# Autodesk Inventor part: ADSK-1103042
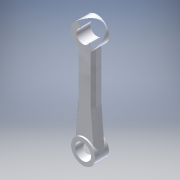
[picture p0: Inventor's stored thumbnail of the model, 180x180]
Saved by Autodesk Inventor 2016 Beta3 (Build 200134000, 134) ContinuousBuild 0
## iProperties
Shininess: 50.0
Length Units: 11272
Angle Units: 11279
Time Units: 11290
Mass Units: 11286
Length Display Precision: 4
Angle Display Precision: 2
Compacted: True
Created: 2000-11
Part Number: ADSK-1103042
Document SubType Name: Modeling
Description: CONNECTING ROD
Mass: 0.815863 g
Surface Area: 4.69105 cm^2
Volume: 0.301057 cm^3
Density: 2.71 g/cm^3
Material: Aluminum-6061
Appearance: Aluminum - Flat
Density: 0.0
Volumn: 0.0
Area: 0.0
PropertySet Name: Model Information
Control State: 0
Master: False
Checked Out: False
Author: Autodesk, Inc.
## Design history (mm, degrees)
node "Extrusion1" dims "d8" = 2.54, "d9" = 0
  sketch "Sketch2"
    geometry: L1 (-7.585, -9.592)-(-6.801, -0.307); L2 (-6.801, -0.307)-(-6.801, 11.849); L3 (-2.674, 11.849)-(-2.674, -0.307); L4 (-2.674, -0.307)-(-1.89, -9.592); C1 r 1.905 at (-4.737, -9.832); C2 r 1.587 at (-4.737, 13.917); C3 r 2.064 at (-4.737, 13.917); A1 r 2.857 centre (-4.737, -9.832) between (-7.585, -9.592) and (-1.89, -9.592); A2 r 2.921 centre (-4.737, 13.917) between (-2.674, 11.849) and (-6.801, 11.849)
    constraints: 8 end point, 5 centre point, 4 point on circle, 4 tangent, 2 coincident, 1 concentric, 1 horizontal alignment, 1 parallel, 1 vertical, 1 vertical alignment, 1 other
    dimensions: "d0" = 3.81 diameter of C1; "d1" = 3.175 diameter of C2; "d2" = 23.749 distance of C1.centre C2.centre; "d3" = 4.1275 diameter of C3; "d5" = 5.715 diameter of A1; "d7" = 9.525 vertical distance of L1.end C1.centre; "d17" = 2.921 radius of A2
node "Extrusion2" dims "d10" = 0.381, "d11" = 0
  sketch "Sketch3"
    geometry: L1 (6.801, -0.307)-(7.585, -9.592) reference; C1 r 1.587 at (4.737, 13.917) reference; C2 r 2.858 at (4.737, -9.832); A1 r 2.857 centre (4.737, -9.832) between (1.89, -9.592) and (7.585, -9.592) reference; A2 r 2.921 centre (4.737, 13.917) between (6.801, 11.849) and (2.674, 11.849) reference; 3 further points
    constraints: 2 coincident, 1 centre point, 1 tangent, 5 other
node "Extrusion3" dims "d12" = 0.381, "d13" = 0
  sketch "Sketch4"
    geometry: A1 r 2.857 centre (-4.737, -9.832) between (-7.585, -9.592) and (-1.89, -9.592) reference; A2 r 2.921 centre (-4.737, 13.917) between (-2.674, 11.849) and (-6.801, 11.849) reference; 6 further points
    constraints: 2 coincident, 10 other
node "Fillet1" dims "d14" = 8.001
node "Chamfer1" dims "d15" = 0.635, "d16" = 0.635, "d18" = 45 deg
workplane "Work Plane1"
body "Solid1"
